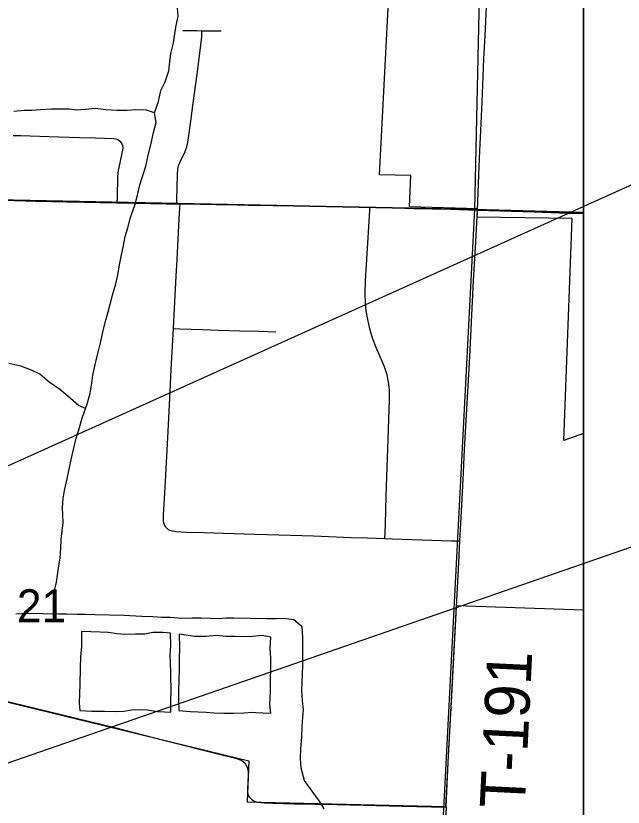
# Model space of a CAD drawing. Extents: x 0 to 34, y 0 to 22.
# Drawn here: x 8.183 to 8.95, y 16.761 to 17.76 of the extents above; entities that cross this region are included whole.
import ezdxf

# ---------------------------------------------------------------- set-up
doc = ezdxf.new("R2010")
doc.units = 0
for name, color, linetype in [('GM_X_City_Street', 7, 'Continuous'), ('GM_X_Corporation', 7, 'Continuous'), ('GM_X_County_Road', 7, 'Continuous'), ('GM_X_Minor_Lake', 7, 'Continuous'), ('GM_X_Minor_River', 7, 'Continuous'), ('GM_X_Section_Text', 7, 'Continuous'), ('GM_X_Township_Road', 7, 'Continuous'), ('GM_X_Township_Road_Text', 7, 'Continuous'), ('SH_Data', 7, 'Continuous')]:
    doc.layers.add(name, color=color, linetype=linetype)

msp = doc.modelspace()

# ---------------------------------------------------------------- linework, layer by layer
at = {"layer": 'GM_X_City_Street'}
for points in [[(8.3866, 17.52287), (8.38665, 17.52853), (8.38679, 17.54304), (8.38716, 17.56044), (8.3877, 17.56664), (8.38863, 17.57087), (8.39063, 17.57609), (8.39695, 17.58892), (8.39906, 17.59475), (8.40031, 17.60019), (8.40423, 17.62726), (8.40693, 17.6501), (8.41199, 17.68642), (8.41788, 17.73329), (8.41802, 17.73729), (8.41817, 17.74142)], [(8.39425, 17.74188), (8.41189, 17.74148), (8.41817, 17.74142), (8.44262, 17.74118)], [(8.18002, 17.60927), (8.18481, 17.60905), (8.18933, 17.60904), (8.23717, 17.60757), (8.26388, 17.60653), (8.28377, 17.60624), (8.3067, 17.60541), (8.30951, 17.60482), (8.3119, 17.60388), (8.31404, 17.60232), (8.31651, 17.59953), (8.31783, 17.59632), (8.31832, 17.59369), (8.31793, 17.59104), (8.31438, 17.57472), (8.31225, 17.56494), (8.31161, 17.55709), (8.31097, 17.53134), (8.3108, 17.52428)], [(8.3733, 17.11372), (8.37182, 17.11561), (8.37075, 17.1178), (8.37, 17.12016), (8.3696, 17.12323), (8.36964, 17.13004), (8.37155, 17.1648), (8.37534, 17.23555), (8.37815, 17.28643), (8.37952, 17.31373), (8.38214, 17.36541), (8.38219, 17.36648), (8.3858, 17.43164), (8.38685, 17.45274), (8.38816, 17.4788), (8.38943, 17.50363), (8.39036, 17.51784), (8.39068, 17.52283)], [(8.64908, 17.10054), (8.64935, 17.10776), (8.64974, 17.11895), (8.65087, 17.15374), (8.65193, 17.19037), (8.65311, 17.22582), (8.65501, 17.27557), (8.65492, 17.28801), (8.65389, 17.2979), (8.65201, 17.30703), (8.64872, 17.31707), (8.64221, 17.33188), (8.638, 17.34158), (8.63366, 17.35325), (8.63014, 17.36518), (8.62751, 17.37671), (8.62571, 17.38776), (8.62474, 17.39766), (8.62429, 17.40948), (8.62484, 17.42564), (8.62997, 17.51457), (8.63019, 17.51848)], [(8.38214, 17.36541), (8.39021, 17.36518), (8.41884, 17.36438), (8.43905, 17.36346), (8.46582, 17.36275), (8.49009, 17.36216), (8.51126, 17.36149)], [(8.3733, 17.11372), (8.37536, 17.11191), (8.37778, 17.1108), (8.38074, 17.10993), (8.38503, 17.10931), (8.39867, 17.10861), (8.42105, 17.10804), (8.44527, 17.10722), (8.48438, 17.10589), (8.50053, 17.10536), (8.5589, 17.10373), (8.6067, 17.10185), (8.62719, 17.10134), (8.64908, 17.10054), (8.65824, 17.1002), (8.73337, 17.09766), (8.74397, 17.09731)]]:
    msp.add_lwpolyline(points, dxfattribs=at)
at = {"layer": 'GM_X_Corporation'}
for points in [[(8.9, 14.49422), (8.9, 20.89996), (2.1, 20.89996)], [(8.9, 14.49422), (8.9, 20.50415)], [(7.92453, 16.95459), (8.4774, 16.81972), (8.47543, 16.7679), (8.72627, 16.76213), (8.73976, 17.0157), (8.9, 17.01054), (8.9, 17.23308), (8.87495, 17.22406), (8.88573, 17.50449), (8.76556, 17.50624), (8.76641, 17.51647), (8.68002, 17.51896), (8.68204, 17.55847), (8.6425, 17.55961), (8.65329, 17.76979)]]:
    msp.add_lwpolyline(points, dxfattribs=at)
for points in [[(7.73457, 18.54715), (8.78463, 18.5318), (8.76248, 17.51563), (7.70158, 17.53728)], [(8.9, 17.51187), (8.9, 18.52947), (8.78463, 18.5318), (8.76248, 17.51563)], [(7.70158, 17.53728), (8.76248, 17.51563), (8.71036, 16.51494), (7.6999, 16.53694)], [(8.9, 16.50862), (8.9, 17.51187), (8.76248, 17.51563), (8.71036, 16.51494)]]:
    msp.add_lwpolyline(points, close=True, dxfattribs=at)
at = {"layer": 'GM_X_County_Road'}
for p, q in [((8.3866, 17.52287), (8.39068, 17.52283)), ((8.39068, 17.52283), (8.41627, 17.52257))]:
    msp.add_line(p, q, dxfattribs=at)
for points in [[(8.06914, 17.53183), (8.08468, 17.53048), (8.09457, 17.53005), (8.12124, 17.52905), (8.16847, 17.52745), (8.20824, 17.52636), (8.24801, 17.52544), (8.3108, 17.52428)], [(8.3108, 17.52428), (8.33319, 17.52387), (8.37295, 17.52301), (8.3866, 17.52287)], [(8.41627, 17.52257), (8.4202, 17.52253), (8.43584, 17.52224), (8.44833, 17.52194), (8.47649, 17.5214)], [(8.47649, 17.5214), (8.48253, 17.52128), (8.56019, 17.51991), (8.61612, 17.51879), (8.63019, 17.51848)], [(8.63019, 17.51848), (8.67454, 17.51751), (8.67997, 17.51729)], [(8.67997, 17.51729), (8.68597, 17.51719), (8.73205, 17.51604), (8.76613, 17.515)], [(8.76613, 17.515), (8.83775, 17.51265), (8.88002, 17.51124), (8.9, 17.51062)], [(8.16436, 16.89675), (8.2248, 16.88199), (8.3079, 16.86167), (8.36965, 16.8458), (8.44512, 16.82702), (8.4573, 16.824), (8.4623, 16.82267), (8.46535, 16.8216), (8.46847, 16.82012), (8.47119, 16.81799), (8.47317, 16.81552), (8.47481, 16.81272), (8.4758, 16.80993), (8.47646, 16.80581), (8.47663, 16.80104), (8.47623, 16.79315), (8.4759, 16.78402), (8.47574, 16.77957), (8.47634, 16.77693), (8.47782, 16.77444), (8.47971, 16.77228), (8.48075, 16.7713), (8.48298, 16.76961), (8.48549, 16.76843), (8.48822, 16.76764), (8.49264, 16.76697), (8.49714, 16.76664), (8.50788, 16.76623), (8.53428, 16.76561), (8.58872, 16.76446), (8.63846, 16.76331), (8.67112, 16.76264), (8.72634, 16.76141)], [(8.72634, 16.76141), (8.72418, 16.71497), (8.7229, 16.68582), (8.72173, 16.66036), (8.71936, 16.61883), (8.71786, 16.57787), (8.7162, 16.54561), (8.71558, 16.52888), (8.71531, 16.51477)]]:
    msp.add_lwpolyline(points, dxfattribs=at)
at = {"layer": 'GM_X_Minor_Lake'}
for points in [[(8.26618, 16.98293), (8.26606, 16.96413), (8.26504, 16.95087), (8.2644, 16.93722), (8.26398, 16.9156), (8.2634, 16.90499), (8.26316, 16.89247), (8.264, 16.88309), (8.27927, 16.88229), (8.29519, 16.88236), (8.30998, 16.88208), (8.31947, 16.88265), (8.32935, 16.88398), (8.33923, 16.88454), (8.34945, 16.88397), (8.36193, 16.88221), (8.37092, 16.8815)], [(8.37092, 16.8815), (8.37874, 16.88121), (8.37879, 16.89099), (8.37921, 16.91299), (8.37902, 16.92286), (8.37884, 16.93311), (8.37827, 16.94261), (8.3781, 16.95362), (8.37871, 16.96537), (8.37839, 16.98077), (8.36879, 16.98188), (8.35627, 16.98174), (8.34599, 16.97966), (8.33423, 16.97951), (8.32096, 16.97939), (8.31073, 16.97997), (8.30015, 16.98169), (8.28954, 16.98227), (8.26618, 16.98293)], [(8.38935, 16.97966), (8.39004, 16.96287), (8.38937, 16.94808), (8.38949, 16.9348), (8.38885, 16.92115), (8.38862, 16.90901), (8.38876, 16.89687), (8.38888, 16.8832), (8.40364, 16.88216), (8.41349, 16.88159), (8.42335, 16.8814), (8.43319, 16.88045), (8.44569, 16.87982), (8.45783, 16.87997), (8.47149, 16.88046), (8.48212, 16.88102), (8.4856, 16.88066)], [(8.4856, 16.88066), (8.50516, 16.87977), (8.50393, 16.89122), (8.5046, 16.90638), (8.50453, 16.92232), (8.50518, 16.93635), (8.50505, 16.94926), (8.50415, 16.96142), (8.50519, 16.97582), (8.49423, 16.97793), (8.48207, 16.97665), (8.47144, 16.97609), (8.46008, 16.97669), (8.44832, 16.97654), (8.43659, 16.97791), (8.42367, 16.97664), (8.40927, 16.97692), (8.38935, 16.97966)]]:
    msp.add_lwpolyline(points, dxfattribs=at)
at = {"layer": 'GM_X_Minor_River'}
for points in [[(8.35833, 17.63786), (8.36315, 17.65219), (8.36607, 17.66579), (8.3716, 17.67707), (8.37641, 17.69064), (8.37777, 17.702), (8.37911, 17.7126), (8.38241, 17.7262), (8.38506, 17.74588), (8.38799, 17.75987), (8.38742, 17.76975)], [(8.23082, 17.00504), (8.23142, 17.01641), (8.23174, 17.03273), (8.23463, 17.04519), (8.23725, 17.06298), (8.23902, 17.07585), (8.24, 17.08759), (8.2406, 17.09897), (8.24157, 17.10995), (8.24291, 17.12055), (8.24234, 17.13005), (8.24214, 17.13954), (8.24312, 17.15091), (8.24484, 17.16112), (8.24815, 17.17586), (8.25109, 17.19022), (8.25442, 17.20571), (8.25938, 17.22687), (8.26262, 17.23743), (8.26667, 17.25102), (8.27029, 17.26195), (8.27352, 17.27176), (8.27716, 17.28383), (8.27931, 17.29669), (8.28063, 17.30653), (8.28396, 17.32165), (8.28768, 17.33752), (8.29056, 17.34922), (8.29348, 17.36283), (8.29677, 17.37605), (8.29963, 17.38662), (8.30534, 17.40738), (8.30941, 17.42173), (8.31189, 17.43268), (8.31404, 17.44592), (8.31614, 17.45651), (8.31906, 17.47011), (8.32118, 17.48146), (8.32442, 17.4924), (8.32809, 17.50561), (8.33332, 17.52107), (8.33619, 17.53202), (8.33988, 17.54675), (8.34352, 17.55845), (8.34716, 17.57052), (8.35046, 17.58412), (8.35375, 17.59734), (8.35708, 17.61284), (8.36037, 17.62567), (8.35833, 17.63786), (8.34815, 17.64109), (8.33488, 17.64135), (8.32388, 17.6408), (8.3106, 17.64068), (8.29697, 17.6417), (8.28334, 17.64311), (8.27118, 17.64182), (8.26018, 17.64128), (8.25034, 17.64223), (8.24048, 17.64241), (8.22834, 17.64227), (8.21429, 17.64141), (8.20329, 17.64086), (8.1938, 17.64066), (8.18088, 17.6394)], [(8.27117, 17.26463), (8.26245, 17.26818), (8.24865, 17.28021), (8.23857, 17.28837), (8.22548, 17.29773), (8.21354, 17.30783), (8.20302, 17.31297), (8.18947, 17.31816), (8.17437, 17.32149)], [(8.5723, 16.75936), (8.56679, 16.76895), (8.55718, 16.78166), (8.54758, 16.79512), (8.54332, 16.81039), (8.54244, 16.8233), (8.54304, 16.83506), (8.54409, 16.84984), (8.54472, 16.86311), (8.54571, 16.87485), (8.54628, 16.8847), (8.54497, 16.89536), (8.54409, 16.90904), (8.54523, 16.92875), (8.54547, 16.94088), (8.54572, 16.95378), (8.54556, 16.96555), (8.54538, 16.97542), (8.54488, 16.98909), (8.53405, 16.99765), (8.52157, 16.99941), (8.51209, 16.99921), (8.49995, 16.99907), (8.45825, 16.99988), (8.44877, 16.99968), (8.43889, 16.99911), (8.42904, 16.9993), (8.4173, 16.99991), (8.40592, 16.99975), (8.39264, 16.99963), (8.37825, 17.00067), (8.36764, 17.00087), (8.35627, 17.00147), (8.34225, 17.00212), (8.31952, 17.00332), (8.28313, 17.00403), (8.27063, 17.00465), (8.26077, 17.00446), (8.2475, 17.00472), (8.23765, 17.00491), (8.19784, 17.00568), (8.18304, 17.00483)]]:
    msp.add_lwpolyline(points, dxfattribs=at)
at = {"layer": 'GM_X_Township_Road'}
msp.add_line((8.76572, 17.50699), (8.76613, 17.515), dxfattribs=at)
for points in [[(8.76613, 17.515), (8.76788, 17.55955), (8.76915, 17.58996), (8.77032, 17.61539), (8.77208, 17.65138), (8.77428, 17.706), (8.77568, 17.73515), (8.77795, 17.78107), (8.77919, 17.81023), (8.78066, 17.83879)], [(8.74397, 17.09731), (8.74512, 17.11919), (8.74697, 17.15832), (8.74844, 17.18376), (8.7498, 17.21296), (8.75625, 17.32967), (8.76122, 17.42592), (8.76408, 17.47496), (8.76572, 17.50699)], [(8.73953, 17.01421), (8.74251, 17.06951), (8.74397, 17.09731)], [(8.72634, 16.76141), (8.72764, 16.79073), (8.72995, 16.83481), (8.73311, 16.8938), (8.73867, 16.99812), (8.73953, 17.01421)]]:
    msp.add_lwpolyline(points, dxfattribs=at)
at = {"layer": 'SH_Data'}
msp.add_line((8.9, 20.89996), (8.9, 14.09996), dxfattribs=at)
msp.add_lwpolyline([(4.57396, 15.57027), (9.28135, 17.20113), (9.28135, 17.69113)], close=True, dxfattribs=at)

# ---------------------------------------------------------------- texts
at = {"layer": 'GM_X_Section_Text'}
msp.add_text('21', height=0.041856, rotation=0.00001, dxfattribs=at).set_placement((8.18455, 16.99447))
at = {"layer": 'GM_X_Township_Road_Text'}
msp.add_text('T-191', height=0.056818, rotation=87.20589, dxfattribs=at).set_placement((8.8256, 16.75882))

doc.saveas('drawing.dxf')
